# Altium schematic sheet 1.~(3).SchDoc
size 420 x 297 mm
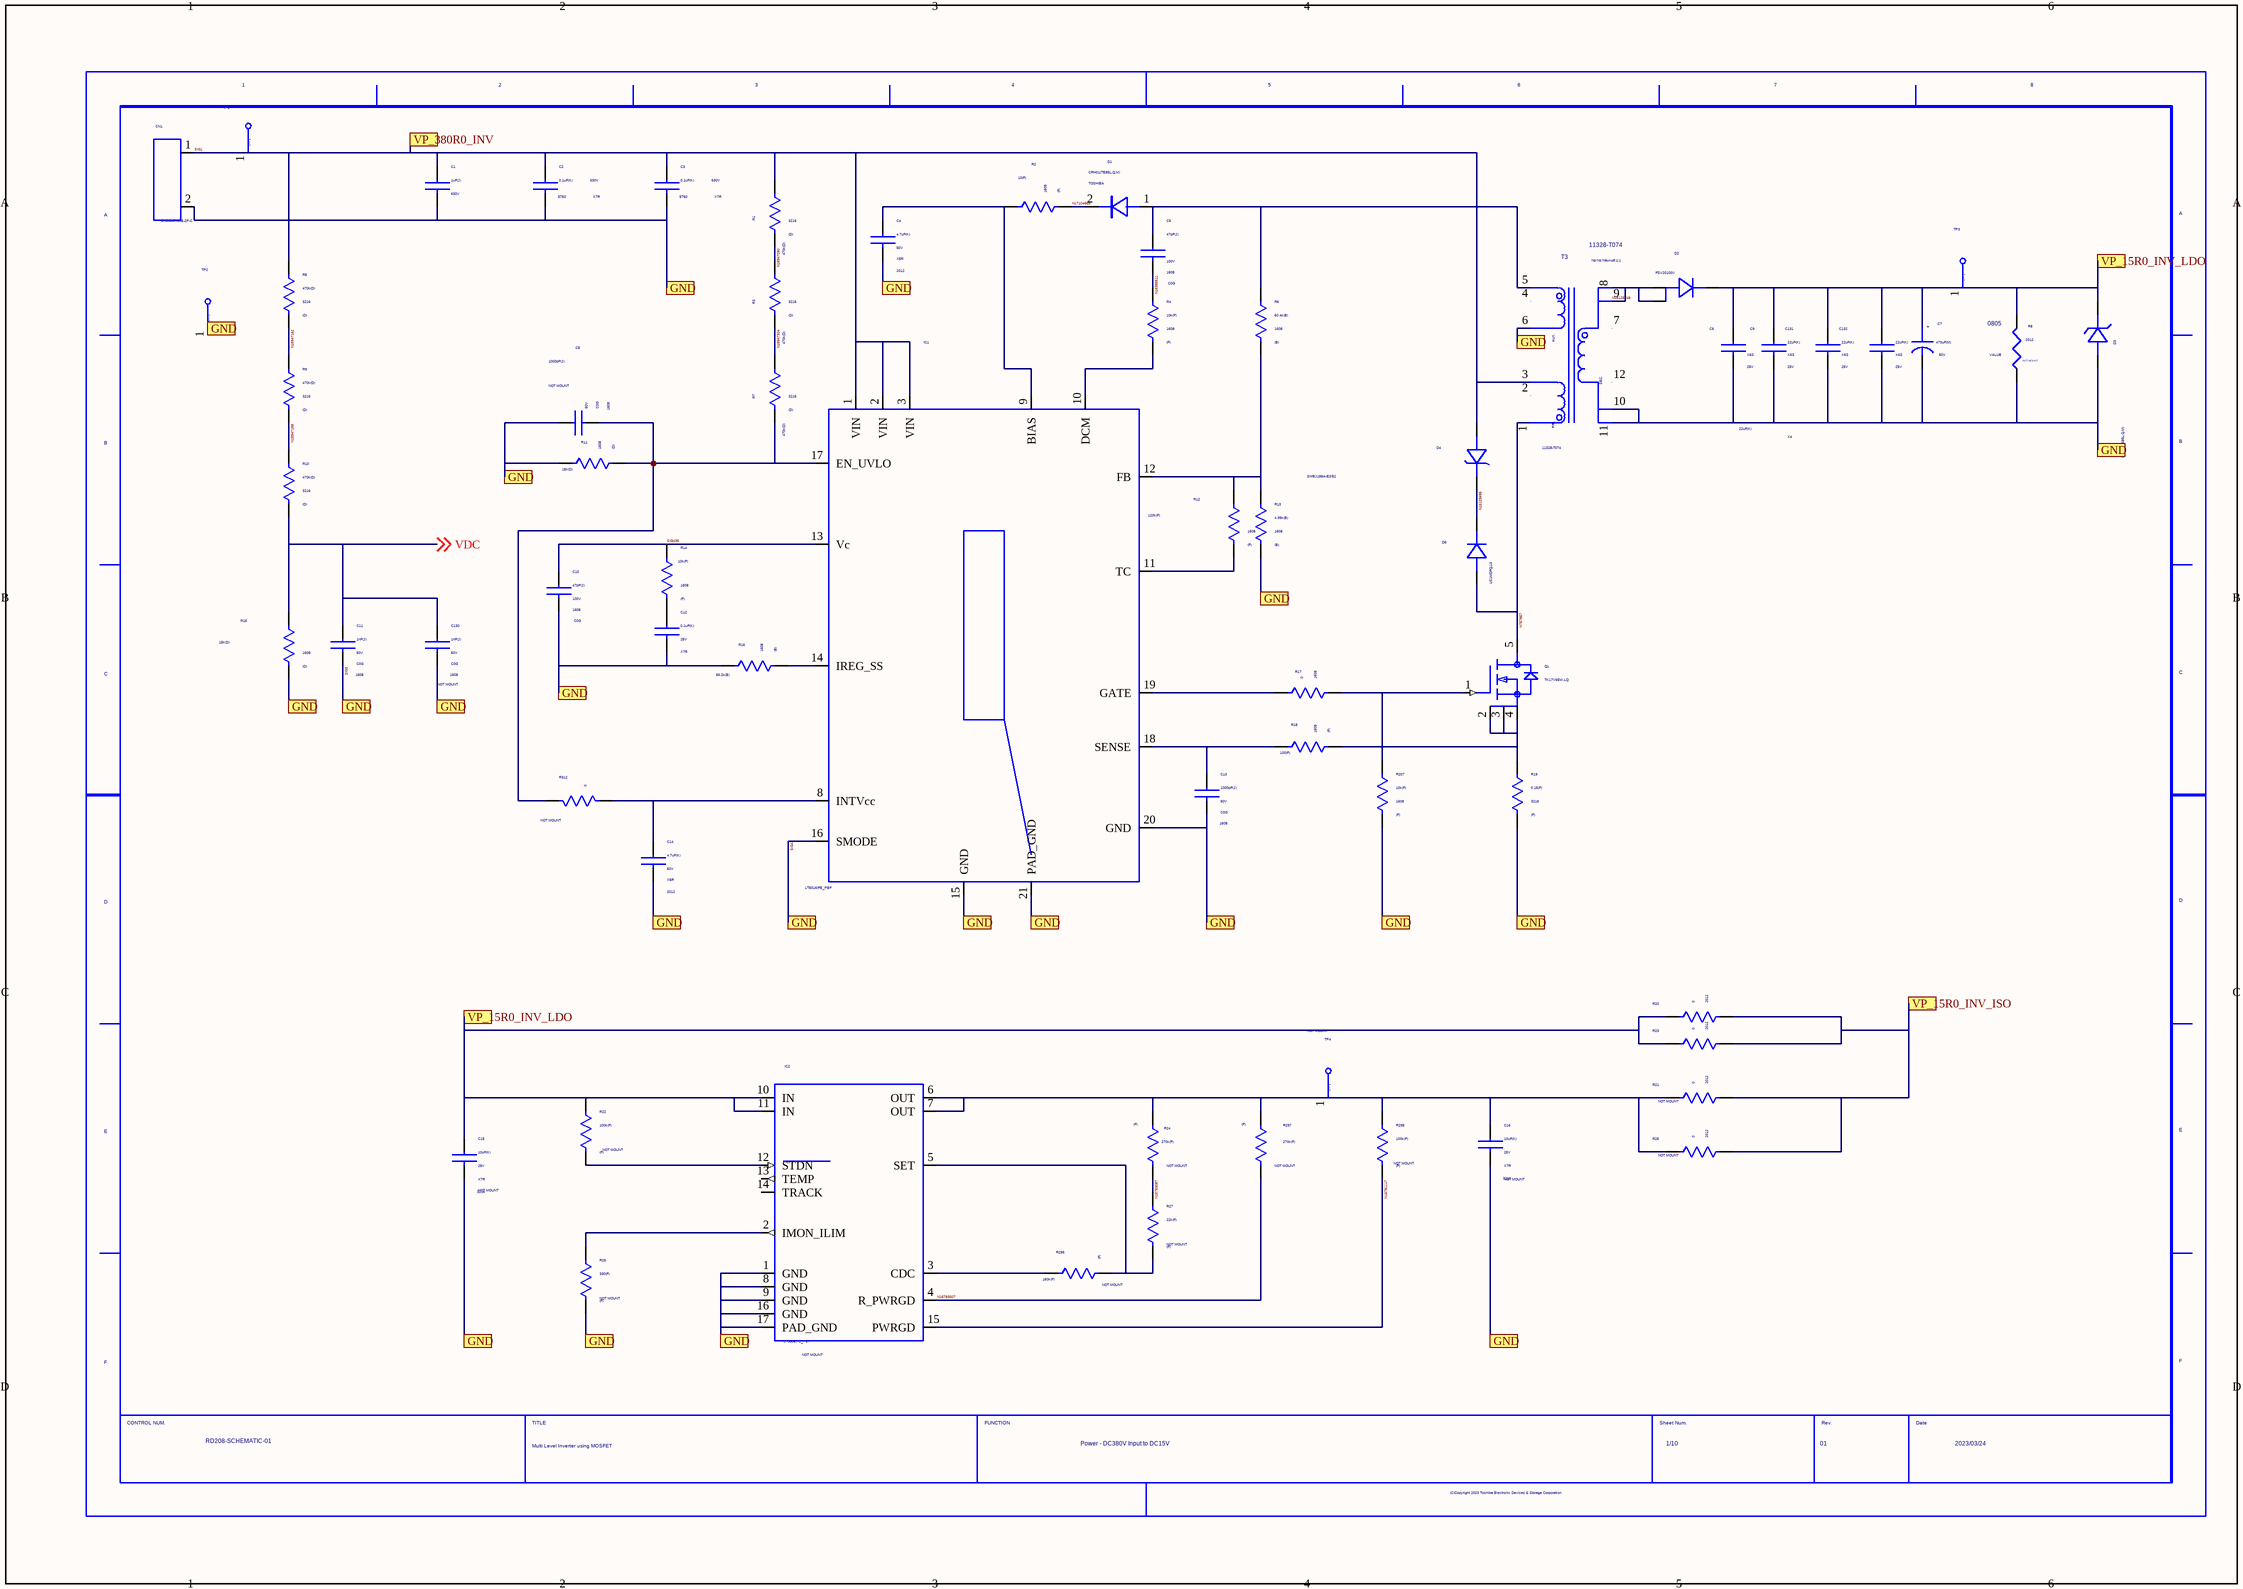
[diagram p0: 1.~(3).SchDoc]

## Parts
C1  VAL2: 630V  VAL1: 1uF(J)  (hidden comment: ECWFG2J105P1)
C2  VAL2: 630V  SIZECODESMD: 5750  VALUE4: X7R  VAL1: 0.1uF(K)  (hidden comment: 2220CC104KAT1A)
C3  VAL2: 630V  SIZECODESMD: 5750  VALUE4: X7R  VAL1: 0.1uF(K)  (hidden comment: 2220CC104KAT1A)
C4  VAL2: 50V  SIZECODESMD: 2012  VALUE4: X5R  VAL1: 4.7uF(K)  (hidden comment: GRM21BR61H475KE51L)
C5  VAL2: 100V  SIZECODESMD: 1608  VALUE4: C0G  VAL1: 47pF(J)  (hidden comment: GRM1885C2A470JA01D)
C6  VAL2: 25V  VALUE4: X6S  VAL1: 22uF(K)  (hidden comment: GRM31CC81E226KE11L)
C7  VAL2: 50V  VAL1: 470uF(M)  (hidden comment: EKY_500ELL471ML15S)
C8  VAL2: 50V  SIZECODESMD: 1608  VALUE4: C0G  VAL1: 1000pF(J)  NOTMOUNT: NOT MOUNT  (hidden comment: GRM1885C1H102JA01J)
C9  VAL2: 25V  VALUE4: X6S  VAL1: 22uF(K)  (hidden comment: GRM31CC81E226KE11L)
C10  VAL2: 100V  SIZECODESMD: 1608  VALUE4: C0G  VAL1: 47pF(J)  (hidden comment: GRM1885C2A470JA01D)
C11  VAL2: 50V  SIZECODESMD: 1608  VALUE4: C0G  VAL1: 1nF(J)  (hidden comment: GRM1885C1H102JA01J)
C12  VAL2: 25V  VALUE4: X7R  VAL1: 0.1uF(K)  (hidden comment: GRM155R71E104KE14D)
C13  VAL2: 50V  SIZECODESMD: 1608  VALUE4: C0G  VAL1: 1000pF(J)  (hidden comment: GRM1885C1H102JA01J)
C14  VAL2: 50V  SIZECODESMD: 2012  VALUE4: X5R  VAL1: 4.7uF(K)  (hidden comment: GRM21BR61H475KE51L)
C15  VAL2: 25V  SIZECODESMD: 3216  VALUE4: X7R  VAL1: 10uF(K)  NOTMOUNT: NOT MOUNT  (hidden comment: GRM31CR71E106MA12K)
C16  VAL2: 25V  SIZECODESMD: 3216  VALUE4: X7R  VAL1: 10uF(K)  NOTMOUNT: NOT MOUNT  (hidden comment: GRM31CR71E106MA12K)
C130  VAL2: 50V  SIZECODESMD: 1608  VALUE4: C0G  VAL1: 1nF(J)  NOTMOUNT: NOT MOUNT  (hidden comment: GRM1885C1H102JA01J)
C131  VAL2: 25V  VALUE4: X6S  VAL1: 22uF(K)  (hidden comment: GRM31CC81E226KE11L)
C132  VAL2: 25V  VALUE4: X6S  VAL1: 22uF(K)  (hidden comment: GRM31CC81E226KE11L)
CN1  VAL1: OTB-640NS-B-2P-C  (hidden comment: OTB_640NS_B_2P_C)
D1  USERCOMPTEXT3: TOSHIBA  VAL3: CRH01(TE85L,Q,M)  (hidden comment: CRH01_TE85L,Q,M_)
D2  FSV20100V  [SOD-323]
D3  VAL3: CRZ18(TE85L,Q,M)  (hidden comment: CRZ18_TE85L,Q,M_)
D4  VAL1: SMBJ188A-E3/52  (hidden comment: SMBJ188A_E3_52)
D6  VAL1: US1MDFQ-13  (hidden comment: US1MDFQ_13)
IC1  LT8316IFE_PBF
IC2  NOTMOUNT: NOT MOUNT  (hidden comment: LT3086IFE_PBF)
Q1  TK17V65W,LQ
R1  SIZECODESMD: 3216  VALUE4: (D)  VAL1: 470k(D)  (hidden comment: HV73V2BTTD4703D)
R2  SIZECODESMD: 1608  VALUE4: (F)  VAL1: 10(F)  (hidden comment: ERJ3EKF10R0V)
R3  SIZECODESMD: 3216  VALUE4: (D)  VAL1: 470k(D)  (hidden comment: HV73V2BTTD4703D)
R4  SIZECODESMD: 1608  VALUE4: (F)  VAL1: 10k(F)  (hidden comment: ERJ3EKF1002V)
R5  SIZECODESMD: 3216  VALUE4: (D)  VAL1: 470k(D)  (hidden comment: HV73V2BTTD4703D)
R6  SIZECODESMD: 1608  VAL1: 60.4k(B)  VLUE4: (B)  (hidden comment: ERA3APB6042V)
R7  SIZECODESMD: 3216  VALUE4: (D)  VAL1: 470k(D)  (hidden comment: HV73V2BTTD4703D)
R8  SIZE: 0805  VAL1: VALUE  SIZECODESMD: 2012  NOTMOUNT: NOT MOUNT  [3216]  (hidden comment: AAC_0805)
R9  SIZECODESMD: 3216  VALUE4: (D)  VAL1: 470k(D)  (hidden comment: HV73V2BTTD4703D)
R10  SIZECODESMD: 3216  VALUE4: (D)  VAL1: 470k(D)  (hidden comment: HV73V2BTTD4703D)
R11  SIZECODESMD: 1608  VALUE4: (D)  VAL1: 15k(D)  (hidden comment: RK73H1JRTTD1502D)
R12  SIZECODESMD: 1608  VALUE4: (F)  VAL1: 120k(F)  (hidden comment: ERJ3EKF1203V)
R13  SIZECODESMD: 1608  VALUE4: (B)  VAL1: 4.99k(B)  (hidden comment: ERA3AEB4991V)
R14  SIZECODESMD: 1608  VALUE4: (F)  VAL1: 10k(F)  (hidden comment: ERJ3EKF1002V)
R15  SIZECODESMD: 1608  VALUE4: (D)  VAL1: 15k(D)  (hidden comment: RK73H1JRTTD1502D)
R16  SIZECODESMD: 1608  VALUE4: (B)  VAL1: 56.2k(B)  (hidden comment: ERA3ARB5622V)
R17  SIZECODESMD: 1608  VAL1: 0  (hidden comment: ERJ3GEY0R00V)
R18  SIZECODESMD: 1608  VALUE4: (F)  VAL1: 100(F)  (hidden comment: ERJ3EKF1000V)
R19  SIZECODESMD: 3216  VALUE4: (F)  VAL1: 0.15(F)  (hidden comment: KRL1632E_M_R150_F_T5)
R20  SIZECODESMD: 2012  VAL1: 0  (hidden comment: ERJ6GEY0R00V)
R21  SIZECODESMD: 2012  VAL1: 0  NOTMOUNT: NOT MOUNT  (hidden comment: ERJ6GEY0R00V)
R22  VALUE4: (F)  VAL1: 100k(F)  NOTMOUNT: NOT MOUNT  (hidden comment: ERJ2RKF1003X)
R23  SIZECODESMD: 2012  VAL1: 0  (hidden comment: ERJ6GEY0R00V)
R24  VALUE4: (F)  VAL1: 270k(F)  NOTMOUNT: NOT MOUNT  (hidden comment: ERJ2RKF2703X)
R25  SIZECODESMD: 2012  VAL1: 0  NOTMOUNT: NOT MOUNT  (hidden comment: ERJ6GEY0R00V)
R26  VALUE4: (F)  VAL1: 330(F)  NOTMOUNT: NOT MOUNT  (hidden comment: ERJ2RKF3300X)
R27  VALUE4: (F)  VAL1: 22k(F)  NOTMOUNT: NOT MOUNT  (hidden comment: ERJ2RKF2202X)
R207  SIZECODESMD: 1608  VALUE4: (F)  VAL1: 10k(F)  (hidden comment: ERJ3EKF1002V)
R295  VALUE4: (F)  VAL1: 100k(F)  NOTMOUNT: NOT MOUNT  (hidden comment: ERJ2RKF1003X)
R296  VALUE4: (F)  VAL1: 160k(F)  NOTMOUNT: NOT MOUNT  (hidden comment: ERJ2RKF1603X)
R297  VALUE4: (F)  VAL1: 270k(F)  NOTMOUNT: NOT MOUNT  (hidden comment: ERJ2RKF2703X)
R312  VAL1: 0  NOTMOUNT: NOT MOUNT  (hidden comment: ERJ2GE0R00X)
T3  VAL2: Np:Ns:Naux=8:1:1  VAL1: 11328-T074  (hidden comment: 11328_T074)
TP1  TP  (value not drawn)
TP2  TP  (value not drawn)
TP3  TP  (value not drawn)
TP4  NOTMOUNT: NOT MOUNT  (hidden comment: TP)
U?  DATE: 2023/03/24  TITLE: Multi Level Inverter using MOSFET  DRAWINGNUMBER: RD208-SCHEMATIC-01  REVISION: 01  SHEETNUMBER: 1/10  FUNCTION: Power - DC380V Input to DC15V  (hidden comment: WAKU_DEF100)

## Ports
GND, VP_15R0_INV_ISO, VP_15R0_INV_LDO, VP_380R0_INV

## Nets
LDO_15V_CDC: IC2.3(CDC) R296.1
LDO_15V_ILIM: IC2.2(IMON_ILIM) R26.1
LDO_15V_SET: IC2.5(SET) R27.2 R296.2
LDO_15V_STD_N: IC2.12(STDN) R22.2
LDO_15VOUT: C16.1 IC2.6(OUT) IC2.7(OUT) R21.1 R24.2 R25.1 R295.1 R297.2 TP4.1
LT8316_BIAS: C4.1 IC1.9(BIAS) R2.1
LT8316_DCM: IC1.10(DCM) R4.2
LT8316_EN: C8.2 IC1.17(EN_UVLO) R7.2 R11.2 R312.2
LT8316_FB: IC1.12(FB) R6.2 R12.1 R13.1
LT8316_FB_B: C5.1 D1.1(A) R6.1 T3.5
LT8316_GATE: IC1.19(GATE) R17.1
LT8316_GATE_B: Q1.1(G) R17.2 R207.1
LT8316_INTVCC: C14.1 IC1.8(INTVcc) R312.1
LT8316_IREG: IC1.14(IREG_SS) R16.2
LT8316_SENSE: C13.1 IC1.18(SENSE) R18.1
LT8316_SENSE_B: Q1.2(S2) Q1.3(S3) Q1.4(S4) R18.2 R19.1
LT8316_TC: IC1.11(TC) R12.2
N757857: D6.A(ANODE) Q1.5(D) T3.1
N15947158: R9.2 R10.1
N15947162: R5.2 R9.1
N15947280: R1.2 R3.1
N15947304: R3.2 R7.1
N16128748: D2.1(ANODE-1) D2.2(ANODE-2) T3.8 T3.9
N16129695: D4.K(CATHODE) D6.K(CATHODE)
N16355511: C5.2 R4.1
N16781117: IC2.15(PWRGD) R295.2
N16783087: R24.1 R27.1
N16783507: IC2.4(R_PWRGD) R297.1
N17104568: D1.2(C) R2.2
SIG1: C1.1 C2.1 C3.1 CN1.1 D4.A(ANODE) IC1.1(VIN) IC1.2(VIN) IC1.3(VIN) R1.1 R5.1 T3.3 TP1.1 ; port VP_380R0_INV
SIG3: C1.2 C2.2 C3.2 C4.2 C6.2 C7.2 C8.1 C9.2 C10.2 C11.2 C12.2 C13.2 C14.2 C15.2 C16.2 C130.2 C131.2 C132.2 CN1.2 D3.A(ANODE) IC1.15(GND) IC1.16(SMODE) IC1.20(GND) IC1.21(PAD_GND) IC2.1(GND) IC2.8(GND) IC2.9(GND) IC2.16(GND) IC2.17(PAD_GND) R8.1 R11.1 R13.2 R15.2 R16.1 R19.2 R26.2 R207.2 T3.6 T3.10 T3.11 TP2.1 ; port GND  [also labelled SIG4]
SIG435: C10.1 IC1.13(Vc) R14.1
VDC: C11.1 C130.1 R10.2 R15.1 ; off-sheet VDC
VP_15R0_INV_ISO: R20.2 R21.2 R23.2 R25.2 ; port VP_15R0_INV_ISO
VP_15R0_INV_LDO: C6.1 C7.1 C9.1 C15.1 C131.1 C132.1 D2.3(CATHODE) D3.K(CATHODE) IC2.10(IN) IC2.11(IN) R8.2 R20.1 R22.1 R23.1 TP3.1 ; port VP_15R0_INV_LDO
NetC12_1: C12.1 R14.2

Not connected (* = marked no-connect by the designer): IC2 13(TEMP) 14(TRACK); T3 2 4 7 12

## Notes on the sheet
- X4

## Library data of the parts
C1 = ECWFG2J105P1: MANUFACTURER: PANASONIC; ITEM: CAP Film; TIME: 08:44:47; UPDATEUSER: t5459927; SAVECOUNT: 1; OriginalSymbolOrigin: (0,0); INSTANCENAME: INS15925304
C2 = 2220CC104KAT1A: MANUFACTURER: AVX; ITEM: CAP Ceramic; TIME: 08:44:47; UPDATEUSER: t5459927; SAVECOUNT: 1; OriginalSymbolOrigin: (0,0); INSTANCENAME: INS16805650
C3 = 2220CC104KAT1A: MANUFACTURER: AVX; ITEM: CAP Ceramic; TIME: 08:44:47; UPDATEUSER: t5459927; SAVECOUNT: 1; OriginalSymbolOrigin: (0,0); INSTANCENAME: INS16806135
C4 = GRM21BR61H475KE51L: MANUFACTURER: MURATA; ITEM: CAP Ceramic; TIME: 08:44:46; UPDATEUSER: t5459927; SAVECOUNT: 1; OriginalSymbolOrigin: (0,0); INSTANCENAME: INS15926838
C5 = GRM1885C2A470JA01D: MANUFACTURER: MURATA; ITEM: CAP Ceramic; TIME: 08:44:47; UPDATEUSER: t5459927; SAVECOUNT: 1; OriginalSymbolOrigin: (0,0); INSTANCENAME: INS15927173
C6 = GRM31CC81E226KE11L: MANUFACTURER: MURATA; ITEM: CAP Ceramic; SIZECODESMD: 3216; TIME: 08:44:47; UPDATEUSER: t5459927; SAVECOUNT: 1; OriginalSymbolOrigin: (0,0); INSTANCENAME: INS16787498
C7 = EKY_500ELL471ML15S: MANUFACTURER: Nippon Chemi-Con; ITEM: CAP ALUM; SIZECODESMD: 16.0mm; COMP: EKY-500ELL471ML15S; TIME: 08:44:47; UPDATEUSER: t5459927; SAVECOUNT: 1; OriginalSymbolOrigin: (0,2540); INSTANCENAME: INS15936364
C8 = GRM1885C1H102JA01J: MANUFACTURER: MURATA; ITEM: CAP Ceramic; TIME: 08:44:47; UPDATEUSER: t5459927; SAVECOUNT: 1; OriginalSymbolOrigin: (0,0); INSTANCENAME: INS16256315
C9 = GRM31CC81E226KE11L: MANUFACTURER: MURATA; ITEM: CAP Ceramic; SIZECODESMD: 3216; TIME: 08:44:47; UPDATEUSER: t5459927; SAVECOUNT: 1; OriginalSymbolOrigin: (0,0); INSTANCENAME: INS16787510
C10 = GRM1885C2A470JA01D: MANUFACTURER: MURATA; ITEM: CAP Ceramic; TIME: 08:44:47; UPDATEUSER: t5459927; SAVECOUNT: 1; OriginalSymbolOrigin: (0,0); INSTANCENAME: INS15928528
C11 = GRM1885C1H102JA01J: MANUFACTURER: MURATA; ITEM: CAP Ceramic; TIME: 08:44:47; UPDATEUSER: t5459927; SAVECOUNT: 1; OriginalSymbolOrigin: (0,0); INSTANCENAME: INS16143125
C12 = GRM155R71E104KE14D: MANUFACTURER: MURATA; ITEM: CAP Ceramic; SIZECODESMD: 1005; TIME: 08:44:45; UPDATEUSER: t5459927; SAVECOUNT: 1; OriginalSymbolOrigin: (0,0); INSTANCENAME: INS15928810
C13 = GRM1885C1H102JA01J: MANUFACTURER: MURATA; ITEM: CAP Ceramic; TIME: 08:44:47; UPDATEUSER: t5459927; SAVECOUNT: 1; OriginalSymbolOrigin: (0,0); INSTANCENAME: INS15928036
C14 = GRM21BR61H475KE51L: MANUFACTURER: MURATA; ITEM: CAP Ceramic; TIME: 08:44:46; UPDATEUSER: t5459927; SAVECOUNT: 1; OriginalSymbolOrigin: (0,0); INSTANCENAME: INS15928288
C15 = GRM31CR71E106MA12K: MANUFACTURER: MURATA; ITEM: CAP Ceramic; TIME: 08:44:46; UPDATEUSER: t5459927; SAVECOUNT: 1; OriginalSymbolOrigin: (0,0); INSTANCENAME: INS3166104
C16 = GRM31CR71E106MA12K: MANUFACTURER: MURATA; ITEM: CAP Ceramic; TIME: 08:44:46; UPDATEUSER: t5459927; SAVECOUNT: 1; OriginalSymbolOrigin: (0,0); INSTANCENAME: INS3166501
C130 = GRM1885C1H102JA01J: MANUFACTURER: MURATA; ITEM: CAP Ceramic; TIME: 08:44:47; UPDATEUSER: t5459927; SAVECOUNT: 1; OriginalSymbolOrigin: (0,0); INSTANCENAME: INS16143791
C131 = GRM31CC81E226KE11L: MANUFACTURER: MURATA; ITEM: CAP Ceramic; SIZECODESMD: 3216; TIME: 08:44:47; UPDATEUSER: t5459927; SAVECOUNT: 1; OriginalSymbolOrigin: (0,0); INSTANCENAME: INS16787460
C132 = GRM31CC81E226KE11L: MANUFACTURER: MURATA; ITEM: CAP Ceramic; SIZECODESMD: 3216; TIME: 08:44:47; UPDATEUSER: t5459927; SAVECOUNT: 1; OriginalSymbolOrigin: (0,0); INSTANCENAME: INS16787472
CN1 = OTB_640NS_B_2P_C: MANUFACTURER: OSADA; ITEM: Connector; VAL2: 11mm   x2; TIME: 08:44:47; UPDATEUSER: t5459927; SAVECOUNT: 1; SAVEAREA0: -10166,-15544,12232,852; OriginalSymbolOrigin: (0,0); INSTANCENAME: INS17151887
D1 = CRH01_TE85L,Q,M_: 5TH PART FIELD: CRH01; ITEM: DIODE; COMP: CRH01-12; TIME: 08:44:47; UPDATEUSER: t5459927; SAVECOUNT: 1; OriginalSymbolOrigin: (0,0); INSTANCENAME: INS760252
D2 = FSV20100V: MANUFACTURER: On semiconductor; COMP: FSV20100V-123; ITEM: DIODE; TIME: 08:44:47; UPDATEUSER: t5459927; SAVECOUNT: 1; OriginalSymbolOrigin: (0,2540); INSTANCENAME: INS15937116
D3 = CRZ18_TE85L,Q,M_: MANUFACTURER: TOSHIBA; COMP: CRZ18; ITEM: DIODE Zener; TIME: 08:44:47; UPDATEUSER: t5459927; SAVECOUNT: 1; OriginalSymbolOrigin: (0,0); INSTANCENAME: INS16129113
D4 = SMBJ188A_E3_52: MANUFACTURER: Vishay; COMP: SMBJ188A-E3_52; ITEM: DIODE TVS; TIME: 08:44:47; UPDATEUSER: t5459927; SAVECOUNT: 1; OriginalSymbolOrigin: (0,0); INSTANCENAME: INS15937273
D6 = US1MDFQ_13: MANUFACTURER: DIODES; ITEM: DIODE; VAL2: 1000V; SIZECODESMD: 1A; TIME: 08:44:47; UPDATEUSER: t5459927; SAVECOUNT: 1; OriginalSymbolOrigin: (0,0); INSTANCENAME: INS16150519
IC1 = LT8316IFE_PBF: MANUFACTURER: Analog Devices; ITEM: IC DCDC; TIME: 08:44:47; UPDATEUSER: PS4_common_PC; UPDATETIME: 14:20:20; SAVECOUNT: 5; SAVEAREA0: -89670,-104109,148818,4559; OriginalSymbolOrigin: (0,0); COMP: LT-20-Lead-Plastic-TSSOP-FE-R-SP-17p
IC2 = LT3086IFE_PBF: MANUFACTURER: Analog Devices; ITEM: LDO; TIME: 08:44:47; UPDATEUSER: PS4_common_PC; UPDATETIME: 14:21:05; SAVECOUNT: 5; SAVEAREA0: -46534,-51518,75335,4012; OriginalSymbolOrigin: (0,0)
Q1 = TK17V65W,LQ: MANUFATURER: TOSHIBA; ITEM: FET; TIME: 08:44:45; UPDATEUSER: t5459927; SAVECOUNT: 1; OriginalSymbolOrigin: (0,0); INSTANCENAME: INS15937568
R1 = HV73V2BTTD4703D: MANUFACTURER: KOA; ITEM: Register; VAL2: 0.33W; TIME: 08:44:45; UPDATEUSER: t5459927; SAVECOUNT: 1; OriginalSymbolOrigin: (0,0); INSTANCENAME: INS16809998
R2 = ERJ3EKF10R0V: MANUFACTURER: Panasonic; ITEM: Register; VAL2: 100mW; TIME: 08:44:45; UPDATEUSER: t5459927; SAVECOUNT: 1; OriginalSymbolOrigin: (0,0); INSTANCENAME: INS17104536
R3 = HV73V2BTTD4703D: MANUFACTURER: KOA; ITEM: Register; VAL2: 0.33W; TIME: 08:44:45; UPDATEUSER: t5459927; SAVECOUNT: 1; OriginalSymbolOrigin: (0,0); INSTANCENAME: INS16810014
R4 = ERJ3EKF1002V: MANUFACTURER: Panasonic; ITEM: Register; VAL2: 100mW; TIME: 08:44:46; UPDATEUSER: t5459927; SAVECOUNT: 1; OriginalSymbolOrigin: (0,0); INSTANCENAME: INS15927083
R5 = HV73V2BTTD4703D: MANUFACTURER: KOA; ITEM: Register; VAL2: 0.33W; TIME: 08:44:45; UPDATEUSER: t5459927; SAVECOUNT: 1; OriginalSymbolOrigin: (0,0); INSTANCENAME: INS16806683
R6 = ERA3APB6042V: MANUFACTURER: Panasonic; ITEM: Register; VAL2: 100mW; TIME: 08:44:47; UPDATEUSER: t5459927; SAVECOUNT: 1; OriginalSymbolOrigin: (0,0); INSTANCENAME: INS15927417
R7 = HV73V2BTTD4703D: MANUFACTURER: KOA; ITEM: Register; VAL2: 0.33W; TIME: 08:44:45; UPDATEUSER: t5459927; SAVECOUNT: 1; OriginalSymbolOrigin: (0,0); INSTANCENAME: INS16810030
R8 = AAC_0805: RES.,OPT,1206; 7TH PART FIELD: RES.,; 4TH PART FIELD: VISHAY,; 3RD PART FIELD: CHIP; 2ND PART FIELD: 1-5%; 5TH PART FIELD: CRCW0805---RT6; 1ST PART FIELD: 1/8W; TIME: 08:44:45; UPDATEUSER: t5459927; SAVECOUNT: 1; OriginalSymbolOrigin: (0,0); INSTANCENAME: INS757555
R9 = HV73V2BTTD4703D: MANUFACTURER: KOA; ITEM: Register; VAL2: 0.33W; TIME: 08:44:45; UPDATEUSER: t5459927; SAVECOUNT: 1; OriginalSymbolOrigin: (0,0); INSTANCENAME: INS16806699
R10 = HV73V2BTTD4703D: MANUFACTURER: KOA; ITEM: Register; VAL2: 0.33W; TIME: 08:44:45; UPDATEUSER: t5459927; SAVECOUNT: 1; OriginalSymbolOrigin: (0,0); INSTANCENAME: INS16806715
R11 = RK73H1JRTTD1502D: MANUFACTURER: KOA; ITEM: Register; VAL2: 100mW; TIME: 08:44:47; UPDATEUSER: t5459927; SAVECOUNT: 1; OriginalSymbolOrigin: (0,0); INSTANCENAME: INS16809511
R12 = ERJ3EKF1203V: MANUFACTURER: Panasonic; ITEM: Register; VAL2: 100mW; TIME: 08:44:47; UPDATEUSER: t5459927; SAVECOUNT: 1; OriginalSymbolOrigin: (0,0); INSTANCENAME: INS15927358
R13 = ERA3AEB4991V: MANUFACTURER: Panasonic; ITEM: Register; VAL2: 100mW; TIME: 08:44:47; UPDATEUSER: t5459927; SAVECOUNT: 1; OriginalSymbolOrigin: (0,0); INSTANCENAME: INS15927488
R14 = ERJ3EKF1002V: MANUFACTURER: Panasonic; ITEM: Register; VAL2: 100mW; TIME: 08:44:46; UPDATEUSER: t5459927; SAVECOUNT: 1; OriginalSymbolOrigin: (0,0); INSTANCENAME: INS15928669
R15 = RK73H1JRTTD1502D: MANUFACTURER: KOA; ITEM: Register; VAL2: 100mW; TIME: 08:44:47; UPDATEUSER: t5459927; SAVECOUNT: 1; OriginalSymbolOrigin: (0,0); INSTANCENAME: INS16808336
R16 = ERA3ARB5622V: MANUFACTURER: Panasonic; ITEM: Register; VAL2: 100mW; TIME: 08:44:47; UPDATEUSER: t5459927; SAVECOUNT: 1; OriginalSymbolOrigin: (0,0); INSTANCENAME: INS15929035
R17 = ERJ3GEY0R00V: MANUFACTURER: Panasonic; ITEM: Register; VAL2: 1/10W; TIME: 08:44:45; UPDATEUSER: t5459927; SAVECOUNT: 1; OriginalSymbolOrigin: (0,0); INSTANCENAME: INS16641918
R18 = ERJ3EKF1000V: MANUFACTURER: Panasonic; ITEM: Register; VAL2: 100mW; TIME: 08:44:47; UPDATEUSER: t5459927; SAVECOUNT: 1; OriginalSymbolOrigin: (0,0); INSTANCENAME: INS15927883
R19 = KRL1632E_M_R150_F_T5: MANUFACTURER: Susumu; ITEM: Register; VAL2: 750mW; COMP: KRL1632E-M-R150-F-T5; TIME: 08:44:47; UPDATEUSER: t5459927; SAVECOUNT: 1; OriginalSymbolOrigin: (0,0); INSTANCENAME: INS16131577
R20 = ERJ6GEY0R00V: MANUFACTURER: Panasonic; ITEM: Register; VAL2: 1/10W; TIME: 08:44:47; UPDATEUSER: t5459927; SAVECOUNT: 1; OriginalSymbolOrigin: (0,0); INSTANCENAME: INS16037390
R21 R25 = ERJ6GEY0R00V: MANUFACTURER: Panasonic; ITEM: Register; VAL2: 1/10W; TIME: 08:44:47; UPDATEUSER: t5459927; SAVECOUNT: 1; OriginalSymbolOrigin: (0,0); INSTANCENAME: INS16037454
R22 = ERJ2RKF1003X: MANUFACTURER: Panasonic; ITEM: Register; VAL2: 100mW; SIZECODESMD: 1005; TIME: 08:44:47; UPDATEUSER: t5459927; SAVECOUNT: 1; OriginalSymbolOrigin: (0,0); INSTANCENAME: INS16779945
R23 = ERJ6GEY0R00V: MANUFACTURER: Panasonic; ITEM: Register; VAL2: 1/10W; TIME: 08:44:47; UPDATEUSER: t5459927; SAVECOUNT: 1; OriginalSymbolOrigin: (0,0); INSTANCENAME: INS16037422
R24 = ERJ2RKF2703X: MANUFACTURER: Panasonic; ITEM: Register; VAL2: 100mW; SIZECODESMD: 1005; TIME: 08:44:47; UPDATEUSER: t5459927; SAVECOUNT: 1; OriginalSymbolOrigin: (0,0); INSTANCENAME: INS16784959
R26 = ERJ2RKF3300X: MANUFACTURER: Panasonic; ITEM: Register; VAL2: 100mW; SIZECODESMD: 1005; TIME: 08:44:47; UPDATEUSER: t5459927; SAVECOUNT: 1; OriginalSymbolOrigin: (0,0); INSTANCENAME: INS16781755
R27 = ERJ2RKF2202X: MANUFACTURER: Panasonic; ITEM: Register; VAL2: 100mW; SIZECODESMD: 1005; TIME: 08:44:47; UPDATEUSER: t5459927; SAVECOUNT: 1; OriginalSymbolOrigin: (0,0); INSTANCENAME: INS16785023
R207 = ERJ3EKF1002V: MANUFACTURER: Panasonic; ITEM: Register; VAL2: 100mW; TIME: 08:44:46; UPDATEUSER: t5459927; SAVECOUNT: 1; OriginalSymbolOrigin: (0,0); INSTANCENAME: INS16642870
R295 = ERJ2RKF1003X: MANUFACTURER: Panasonic; ITEM: Register; VAL2: 100mW; SIZECODESMD: 1005; TIME: 08:44:47; UPDATEUSER: t5459927; SAVECOUNT: 1; OriginalSymbolOrigin: (0,0); INSTANCENAME: INS16779929
R296 = ERJ2RKF1603X: MANUFACTURER: Panasonic; ITEM: Register; VAL2: 100mW; SIZECODESMD: 1005; TIME: 08:44:47; UPDATEUSER: t5459927; SAVECOUNT: 1; OriginalSymbolOrigin: (0,0); INSTANCENAME: INS16782609
R297 = ERJ2RKF2703X: MANUFACTURER: Panasonic; ITEM: Register; VAL2: 100mW; SIZECODESMD: 1005; TIME: 08:44:47; UPDATEUSER: t5459927; SAVECOUNT: 1; OriginalSymbolOrigin: (0,0); INSTANCENAME: INS16783015
R312 = ERJ2GE0R00X: MANUFACTURER: Panasonic; ITEM: Register; VAL2: 1/10W; SIZECODESMD: 1005; TIME: 08:44:45; UPDATEUSER: t5459927; SAVECOUNT: 1; OriginalSymbolOrigin: (0,0); INSTANCENAME: INS17205038
T3 = 11328_T074: MANUFACTURER: SUMIDA; ITEM: Transformer; TIME: 08:44:47; UPDATEUSER: PS4_common_PC; UPDATETIME: 15:04:11; SAVECOUNT: 3; SAVEAREA0: -40366,-32840,49907,8293; OriginalSymbolOrigin: (-2540,2540)
TP1-TP4 = TP: TIME: 16:12:21; UPDATEUSER: fukuda-y; UPDATETIME: 16:18:11; SAVECOUNT: 2; SAVEAREA0: -242,-92,12810,7836; OriginalSymbolOrigin: (0,7620); VAL3: TH Hole dia. 1.0; COMP: TP-TH1.0-L1.6
U? = WAKU_DEF100: PLOTTIME: HH:MM; SAVEAREA0: 185750,-43960,448537,75779; TIME: 14:30:25; UPDATEUSER: PS4_common_PC; UPDATETIME: 08:22:28; SAVECOUNT: 8; OriginalSymbolOrigin: (10160,284480)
